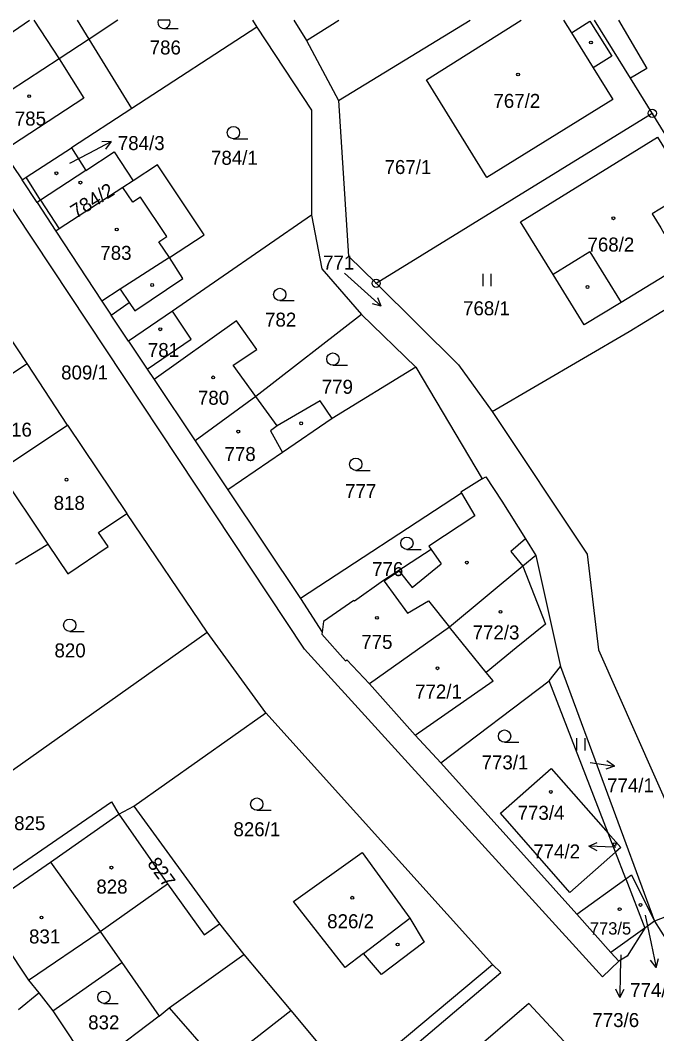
# Model space of a CAD drawing. Extents: x -776606 to -776076, y -974328 to -973875.
# Drawn here: x -776271.1 to -776193.8, y -973997.7 to -973874.5 of the extents above; entities that cross this region are included whole.
import ezdxf

# ---------------------------------------------------------------- set-up
doc = ezdxf.new("R2010")
doc.units = 0
for name, color, linetype in [('Hranice parcel', 7, 'Continuous'), ('Parcelní čísla', 7, 'Continuous'), ('Pop  PČ popisy', 7, 'Continuous'), ('Vnitřní kresba', 7, 'Continuous'), ('Značky bodu BP', 7, 'Continuous'), ('Značky budov', 7, 'Continuous'), ('Značky kultur', 7, 'Continuous')]:
    doc.layers.add(name, color=color, linetype=linetype)

msp = doc.modelspace()

# ---------------------------------------------------------------- linework, layer by layer
at = {"layer": 'Hranice parcel'}
for p, q in [((-776262.79, -973876.85), (-776264.21, -973874.54)), ((-776242.91, -973874.54), (-776242.38, -973875.37)), ((-776237.92, -973874.54), (-776236.37, -973876.99)), ((-776232.47, -973884.28), (-776216.47, -973874.54)), ((-776196.99, -973881.56), (-776201.37, -973874.54)), ((-776242.38, -973875.37), (-776257.6, -973885.27)), ((-776257.6, -973885.27), (-776262.79, -973876.85)), ((-776236.37, -973876.99), (-776232.47, -973884.28)), ((-776194.35, -973885.85), (-776196.99, -973881.56)), ((-776257.6, -973885.27), (-776264.93, -973890.05)), ((-776227.9, -973906.51), (-776194.35, -973885.85)), ((-776183.26, -973903.85), (-776194.35, -973885.85)), ((-776264.93, -973890.05), (-776263.18, -973892.81)), ((-776269.1, -973896.7), (-776270.91, -973893.94)), ((-776269.1, -973896.7), (-776266.82, -973900.17)), ((-776235.77, -973898.22), (-776252.65, -973909.91)), ((-776257.98, -973913.55), (-776260.09, -973910.39)), ((-776252.65, -973909.91), (-776257.98, -973913.55)), ((-776229.69, -973910.31), (-776242.52, -973920.28)), ((-776229.69, -973910.31), (-776223.06, -973916.72)), ((-776257.98, -973913.55), (-776255.73, -973916.95)), ((-776265.39, -973923.75), (-776270.29, -973916.24)), ((-776255.73, -973916.95), (-776254.89, -973918.2)), ((-776223.06, -973916.72), (-776233.23, -973922.95)), ((-776223.06, -973916.72), (-776215, -973930.29)), ((-776254.89, -973918.2), (-776249.88, -973925.66)), ((-776242.52, -973920.28), (-776249.88, -973925.66)), ((-776233.23, -973922.95), (-776234.71, -973920.78)), ((-776233.23, -973922.95), (-776239.28, -973927.09)), ((-776265.39, -973923.75), (-776258.19, -973934.5)), ((-776249.88, -973925.66), (-776245.91, -973931.61)), ((-776239.28, -973927.09), (-776245.91, -973931.61)), ((-776215, -973930.29), (-776214.56, -973930.02)), ((-776245.91, -973931.61), (-776237.1, -973944.84)), ((-776217.53, -973932.01), (-776237.1, -973944.84)), ((-776248.44, -973948.9), (-776258.19, -973934.5)), ((-776208.49, -973939.59), (-776210.07, -973940.9)), ((-776208.49, -973939.59), (-776205.5, -973953.09)), ((-776210.07, -973940.9), (-776219, -973948.3)), ((-776237.1, -973944.84), (-776234.47, -973948.93)), ((-776273.08, -973966.36), (-776248.44, -973948.9)), ((-776241.31, -973958.73), (-776248.44, -973948.9)), ((-776219, -973948.3), (-776228.72, -973955.21)), ((-776231.48, -973952.27), (-776228.72, -973955.21)), ((-776206.87, -973954.83), (-776205.5, -973953.09)), ((-776205.5, -973953.09), (-776194.09, -973984.05)), ((-776220.04, -973964.78), (-776206.87, -973954.83)), ((-776199.71, -973973.36), (-776206.87, -973954.83)), ((-776257.34, -973970.07), (-776241.31, -973958.73)), ((-776203.53, -973983.2), (-776220.04, -973964.78)), ((-776267.49, -973976.87), (-776259.16, -973971.03)), ((-776259.16, -973971.03), (-776257.34, -973970.07)), ((-776257.34, -973970.07), (-776246.94, -973984.38)), ((-776198.82, -973975.67), (-776199.71, -973973.36)), ((-776197.57, -973978.91), (-776198.82, -973975.67)), ((-776275.87, -973982.65), (-776267.49, -973976.87)), ((-776203.53, -973983.2), (-776197.57, -973978.91)), ((-776197.57, -973978.91), (-776195.26, -973984.89)), ((-776199.38, -973987.83), (-776203.53, -973983.2)), ((-776246.94, -973984.38), (-776243.98, -973988.1)), ((-776194.09, -973984.05), (-776195.26, -973984.89)), ((-776194.09, -973984.05), (-776186.87, -973995.48)), ((-776195.26, -973984.89), (-776199.38, -973987.83)), ((-776253.07, -973994.57), (-776243.98, -973988.1)), ((-776267.2, -973994.95), (-776258.81, -973989.08)), ((-776258.81, -973989.08), (-776254.25, -973995.57)), ((-776271.38, -973994.77), (-776268.9, -973992.75)), ((-776268.9, -973992.75), (-776267.2, -973994.95)), ((-776254.25, -973995.57), (-776253.07, -973994.57)), ((-776254.25, -973995.57), (-776261.3, -974000.9))]:
    msp.add_line(p, q, dxfattribs=at)
for points in [[(-776259.27, -973874.54), (-776262.79, -973876.85)], [(-776236.37, -973876.99), (-776232.44, -973874.54)], [(-776221.8, -973881.78), (-776210.26, -973874.54)], [(-776205.13, -973874.54), (-776204.18, -973876.06), (-776201.92, -973874.65), (-776199.26, -973878.91), (-776201.52, -973880.32), (-776199.13, -973884.16), (-776214.43, -973893.65), (-776221.8, -973881.78)], [(-776198.46, -973874.54), (-776195, -973880.4), (-776196.99, -973881.56)], [(-776242.38, -973875.37), (-776235.75, -973885.47), (-776235.77, -973898.22)], [(-776262.79, -973876.85), (-776266.42, -973879.21), (-776276.39, -973885.7)], [(-776232.47, -973884.28), (-776231.24, -973903.2), (-776227.9, -973906.51)], [(-776276.39, -973885.7), (-776273.25, -973890.47), (-776270.91, -973893.94)], [(-776206.39, -973905.45), (-776210.35, -973899.05), (-776193.72, -973888.77), (-776189.72, -973895.24), (-776194.36, -973898.08), (-776193.32, -973899.78), (-776192.94, -973900.4), (-776191.5, -973900.38), (-776189.96, -973902.86), (-776190.65, -973904.27), (-776198.11, -973908.86), (-776202.61, -973911.57), (-776206.39, -973905.45)], [(-776270.91, -973893.94), (-776270.43, -973893.62), (-776264.93, -973890.05)], [(-776263.18, -973892.81), (-776259.73, -973890.53), (-776257.44, -973894.05)], [(-776251.41, -973905.92), (-776253.03, -973903.37), (-776248.81, -973900.64), (-776254.47, -973892.12), (-776257.44, -973894.05)], [(-776263.18, -973892.81), (-776268.67, -973896.42), (-776269.1, -973896.7)], [(-776257.44, -973894.05), (-776258.67, -973894.86), (-776266.4, -973899.9), (-776266.82, -973900.17)], [(-776235.77, -973898.22), (-776234.49, -973904.75), (-776229.69, -973910.31)], [(-776266.82, -973900.17), (-776261.23, -973908.67), (-776260.09, -973910.39)], [(-776213.8, -973922.1), (-776197.17, -973912.38), (-776183.26, -973903.85)], [(-776260.09, -973910.39), (-776257.91, -973908.86), (-776257.23, -973909.86), (-776251.41, -973905.92)], [(-776227.9, -973906.51), (-776217.91, -973916.41), (-776213.8, -973922.1)], [(-776270.29, -973916.24), (-776275.61, -973908.29), (-776276.31, -973907.24)], [(-776255.73, -973916.95), (-776250.38, -973913.32), (-776252.65, -973909.91)], [(-776242.52, -973920.28), (-776245.28, -973916.46), (-776242.4, -973914.54), (-776244.86, -973911.08), (-776254.89, -973918.2)], [(-776281.65, -973923.77), (-776278.7, -973921.8), (-776270.29, -973916.24)], [(-776234.71, -973920.78), (-776239.94, -973923.85), (-776242.52, -973920.28)], [(-776213.8, -973922.1), (-776202.27, -973939.42), (-776200.89, -973951.06), (-776189.59, -973976.54)], [(-776276.73, -973931.11), (-776273.8, -973929.3), (-776265.39, -973923.75)], [(-776215, -973930.29), (-776217.59, -973931.91), (-776217.53, -973932.01)], [(-776214.56, -973930.02), (-776212.64, -973932.99), (-776209.77, -973937.56), (-776208.49, -973939.59)], [(-776217.53, -973932.01), (-776215.92, -973934.78), (-776221.49, -973938.47), (-776221.22, -973938.85)], [(-776271.71, -973940.6), (-776267.81, -973938.2), (-776265.38, -973941.82), (-776260.46, -973938.49), (-776261.64, -973936.79), (-776258.19, -973934.5)], [(-776221.22, -973938.85), (-776226.99, -973942.64), (-776230.52, -973945.14)], [(-776210.07, -973940.9), (-776207.31, -973947.95), (-776210.89, -973950.8), (-776214.54, -973953.81), (-776219, -973948.3)], [(-776230.52, -973945.14), (-776230.63, -973945.06), (-776234.28, -973947.62), (-776234.47, -973948.93)], [(-776234.47, -973948.93), (-776234.5, -973949.16), (-776231.62, -973952.39), (-776231.48, -973952.27)], [(-776228.72, -973955.21), (-776223.16, -973961.44), (-776220.04, -973964.78)], [(-776230.92, -974003.68), (-776213.75, -973989.29), (-776241.31, -973958.73)], [(-776198.82, -973975.67), (-776204.36, -973980.57), (-776212.78, -973970.92), (-776206.63, -973965.5), (-776199.71, -973973.36)], [(-776259.16, -973971.03), (-776253.26, -973979.51), (-776248.81, -973985.69), (-776246.94, -973984.38)], [(-776199.71, -973973.36), (-776198.18, -973975.1), (-776198.82, -973975.67)], [(-776229.6, -973975.7), (-776223.82, -973983.68), (-776222.05, -973986.58), (-776227.23, -973990.52), (-776229.42, -973987.99), (-776231.67, -973989.69), (-776237.93, -973981.67), (-776229.6, -973975.7)], [(-776267.49, -973976.87), (-776261.42, -973985.31), (-776258.81, -973989.08)], [(-776197.57, -973978.91), (-776196.89, -973978.42), (-776194.09, -973984.05)], [(-776275.87, -973982.65), (-776270.15, -973991.2), (-776268.9, -973992.75)], [(-776195.26, -973984.89), (-776197.38, -973988.31), (-776198.41, -973988.91), (-776199.38, -973987.83)], [(-776243.98, -973988.1), (-776238.25, -973994.88), (-776230.92, -974003.68)], [(-776253.07, -973994.57), (-776247.18, -974001.31), (-776246.82, -974001.54), (-776239.27, -974010.62)], [(-776196.71, -974013.25), (-776196.28, -974011.91), (-776198.67, -974005.55), (-776209.34, -973994.03), (-776223.84, -974006.53)], [(-776267.2, -973994.95), (-776262.7, -974001.7), (-776261.3, -974000.9)]]:
    msp.add_lwpolyline(points, dxfattribs=at)
at = {"layer": 'Pop  PČ popisy'}
for p, q in [((-776262.77, -973890.7), (-776260.12, -973889.29)), ((-776260.12, -973889.29), (-776261.24, -973889.32)), ((-776260.12, -973889.29), (-776260.77, -973890.2)), ((-776265.11, -973891.92), (-776262.77, -973890.7)), ((-776201.9, -973964.75), (-776198.94, -973965.22)), ((-776198.94, -973965.22), (-776199.85, -973964.57)), ((-776198.94, -973965.22), (-776200, -973965.56)), ((-776202.06, -973974.94), (-776201.04, -973974.47)), ((-776199.06, -973975.04), (-776202.06, -973974.94)), ((-776202.06, -973974.94), (-776201.08, -973975.47)), ((-776198.77, -973975.06), (-776199.06, -973975.04)), ((-776195.21, -973983.31), (-776194.49, -973986.74)), ((-776194.49, -973986.74), (-776193.87, -973989.68)), ((-776198.18, -973988.13), (-776198.24, -973990.31)), ((-776193.87, -973989.68), (-776194.56, -973988.8)), ((-776193.87, -973989.68), (-776193.58, -973988.59)), ((-776198.24, -973990.31), (-776198.29, -973993.31)), ((-776198.29, -973993.31), (-776198.78, -973992.3)), ((-776198.29, -973993.31), (-776197.77, -973992.32))]:
    msp.add_line(p, q, dxfattribs=at)
at = {"layer": 'Vnitřní kresba'}
for p, q in [((-776236.59, -973950.99), (-776287.26, -973874.54)), ((-776279.55, -973880.99), (-776270.01, -973874.54)), ((-776269.49, -973874.54), (-776266.42, -973879.21)), ((-776204.18, -973876.06), (-776201.52, -973880.32)), ((-776266.42, -973879.21), (-776263.44, -973884)), ((-776263.44, -973884), (-776273.25, -973890.47)), ((-776268.67, -973896.42), (-776270.43, -973893.62)), ((-776257.48, -973896.64), (-776258.67, -973894.86)), ((-776256.54, -973896.05), (-776257.48, -973896.64)), ((-776253.35, -973900.84), (-776256.54, -973896.05)), ((-776268.67, -973896.42), (-776266.4, -973899.9)), ((-776254.3, -973901.46), (-776253.35, -973900.84)), ((-776253.03, -973903.37), (-776254.3, -973901.46)), ((-776253.03, -973903.37), (-776258.99, -973907.22)), ((-776201.93, -973902.69), (-776206.39, -973905.45)), ((-776201.93, -973902.69), (-776198.11, -973908.86)), ((-776258.99, -973907.22), (-776261.23, -973908.67)), ((-776258.99, -973907.22), (-776257.91, -973908.86)), ((-776239.94, -973923.85), (-776240.75, -973924.45)), ((-776240.75, -973924.45), (-776239.28, -973927.09)), ((-776273.8, -973929.3), (-776267.81, -973938.2)), ((-776209.77, -973937.56), (-776211.54, -973939.13)), ((-776221.22, -973938.85), (-776219.98, -973940.61)), ((-776211.54, -973939.13), (-776210.07, -973940.9)), ((-776225.11, -973941.52), (-776226.93, -973942.72)), ((-776225.11, -973941.52), (-776223.53, -973943.48)), ((-776223.53, -973943.48), (-776219.98, -973940.61)), ((-776226.99, -973942.64), (-776226.93, -973942.72)), ((-776226.93, -973942.72), (-776224.1, -973946.6)), ((-776224.1, -973946.6), (-776221.55, -973945.1)), ((-776221.55, -973945.1), (-776219, -973948.3)), ((-776200.39, -973990.8), (-776236.59, -973950.99)), ((-776213.7, -973954.84), (-776214.54, -973953.81)), ((-776223.16, -973961.44), (-776213.7, -973954.84)), ((-776302.45, -973998.67), (-776260.07, -973969.53)), ((-776260.07, -973969.53), (-776259.16, -973971.03)), ((-776261.42, -973985.31), (-776253.26, -973979.51)), ((-776191.35, -973982.98), (-776194.09, -973984.05)), ((-776229.42, -973987.99), (-776223.82, -973983.68)), ((-776270.15, -973991.2), (-776261.42, -973985.31)), ((-776212.73, -973990.29), (-776213.75, -973989.29)), ((-776198.41, -973988.91), (-776200.39, -973990.8)), ((-776246.47, -974018.84), (-776212.73, -973990.29)), ((-776246.82, -974001.54), (-776238.25, -973994.88))]:
    msp.add_line(p, q, dxfattribs=at)
at = {"layer": 'Značky bodu BP'}
for centre, radius in [((-776194.35, -973885.85), 0.5), ((-776194.35, -973885.85), 0.0303), ((-776227.9, -973906.51), 0.5), ((-776227.9, -973906.51), 0.0303)]:
    msp.add_circle(centre, radius, dxfattribs=at)
at = {"layer": 'Značky budov'}
for centre in [(-776201.8, -973877.25), (-776210.66, -973881.13), (-776270.06, -973883.77), (-776266.76, -973893.14), (-776263.84, -973894.27), (-776199.07, -973898.61), (-776259.42, -973899.98), (-776255.12, -973906.72), (-776202.22, -973906.96), (-776254.13, -973912.1), (-776247.71, -973917.95), (-776244.65, -973924.54), (-776237.01, -973923.53), (-776265.53, -973930.38), (-776216.88, -973940.46), (-776212.79, -973946.45), (-776227.8, -973947.17), (-776220.44, -973953.3), (-776206.67, -973968.33), (-776198.92, -973974.7), (-776260.07, -973977.53), (-776230.8, -973981.19), (-776195.77, -973982.07), (-776268.56, -973983.59), (-776198.31, -973982.59), (-776225.29, -973986.88)]:
    msp.add_circle(centre, 0.175, dxfattribs=at)
at = {"layer": 'Značky kultur'}
for p, q in [((-776252.99, -973874.54), (-776254.4, -973874.54)), ((-776253.69, -973875.54), (-776251.94, -973875.54)), ((-776245.24, -973888.95), (-776243.49, -973888.95)), ((-776231.75, -973905.28), (-776227.29, -973909.3)), ((-776214.91, -973906.85), (-776214.91, -973905.35)), ((-776213.91, -973906.85), (-776213.91, -973905.35)), ((-776227.29, -973909.3), (-776227.68, -973908.27)), ((-776239.61, -973908.62), (-776237.86, -973908.62)), ((-776227.29, -973909.3), (-776228.35, -973909.01)), ((-776233.15, -973916.47), (-776231.4, -973916.47)), ((-776230.37, -973929.26), (-776228.62, -973929.26)), ((-776224.17, -973938.85), (-776222.42, -973938.85)), ((-776265.14, -973948.82), (-776263.39, -973948.82)), ((-776212.3, -973962.3), (-776210.55, -973962.3)), ((-776203.5, -973963.3), (-776203.5, -973961.8)), ((-776202.5, -973963.3), (-776202.5, -973961.8)), ((-776242.41, -973970.56), (-776240.66, -973970.56)), ((-776260.98, -973994.03), (-776259.23, -973994.03))]:
    msp.add_line(p, q, dxfattribs=at)
for centre in [(-776245.24, -973888.2), (-776239.61, -973907.87), (-776233.15, -973915.72), (-776230.37, -973928.51), (-776224.17, -973938.1), (-776265.14, -973948.07), (-776212.3, -973961.55), (-776242.41, -973969.81), (-776260.98, -973993.28)]:
    msp.add_circle(centre, 0.75, dxfattribs=at)
msp.add_arc((-776253.69, -973874.79), 0.75, 160.6871, 19.3129, dxfattribs=at)

# ---------------------------------------------------------------- texts
at = {"layer": 'Parcelní čísla'}
for s, height, p in [('786', 1.7, (-776255.42, -973878.7)), ('767/2', 1.7, (-776213.65, -973885.19)), ('785', 1.7, (-776271.81, -973887.34)), ('784/3', 1.7, (-776259.29, -973890.32)), ('784/1', 1.7, (-776247.97, -973892.11)), ('767/1', 1.7, (-776226.88, -973893.23)), ('768/2', 1.7, (-776202.22, -973902.65)), ('783', 1.7, (-776261.42, -973903.66)), ('771', 1.7, (-776234.35, -973904.85)), ('768/1', 1.7, (-776217.34, -973910.4)), ('782', 1.7, (-776241.4, -973911.78)), ('781', 1.7, (-776255.64, -973915.47)), ('809/1', 1.7, (-776266.18, -973918.2)), ('779', 1.7, (-776234.51, -973919.94)), ('780', 1.7, (-776249.56, -973921.27)), ('816', 1.7, (-776273.53, -973925.15)), ('778', 1.7, (-776246.33, -973928.11)), ('777', 1.7, (-776231.68, -973932.62)), ('818', 1.7, (-776267.09, -973934.06)), ('776', 1.7, (-776228.39, -973942.1)), ('772/3', 1.7, (-776216.18, -973949.8)), ('820', 1.7, (-776266.99, -973951.98)), ('775', 1.7, (-776229.71, -973950.95)), ('772/1', 1.7, (-776223.17, -973956.98)), ('773/1', 1.7, (-776215.09, -973965.59)), ('774/1', 1.7, (-776199.84, -973968.38)), ('773/4', 1.7, (-776210.71, -973971.72)), ('825', 1.7, (-776271.89, -973972.98)), ('826/1', 1.7, (-776245.24, -973973.72)), ('774/2', 1.7, (-776208.81, -973976.42)), ('828', 1.7, (-776261.9, -973980.69)), ('826/2', 1.7, (-776233.85, -973984.9)), ('773/5', 1.5, (-776201.93, -973985.67)), ('831', 1.7, (-776270.08, -973986.75)), ('774/3', 1.7, (-776197.03, -973993.26)), ('832', 1.7, (-776262.89, -973997.19)), ('773/6', 1.7, (-776201.63, -973996.91))]:
    msp.add_text(s, height=height, dxfattribs=at).set_placement(p)
for s, rotation, p in [('784/2', 32, (-776264.37, -973898.68)), ('827', 306, (-776255.78, -973977.06))]:
    msp.add_text(s, height=1.7, rotation=rotation, dxfattribs=at).set_placement(p)

doc.saveas('drawing.dxf')
